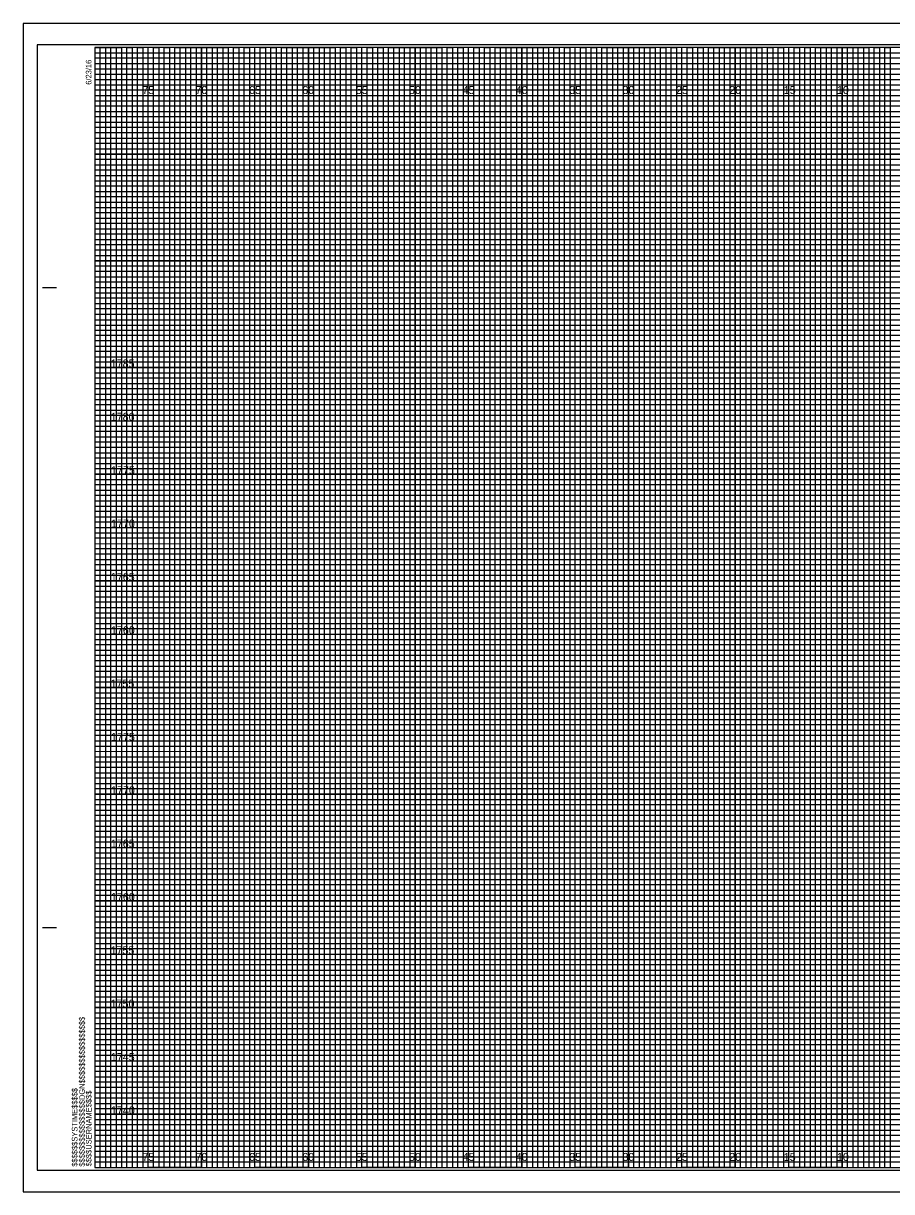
# Model space of a CAD drawing. Extents: x 224 to 392, y 1 to 440.
# Drawn here: x 223.6 to 304.9, y 221 to 330.5 of the extents above; entities that cross this region are included whole.
import ezdxf

# ---------------------------------------------------------------- set-up
doc = ezdxf.new("R2010")
doc.units = 0
for name, color, linetype in [('Prop Grid Mask', 7, 'Continuous'), ('Prop XS Elevation Labels', 7, 'Continuous'), ('Sheet Cross Section CELL', 7, 'Continuous'), ('Sheet Cross Section Grid Major CELL', 7, 'Continuous'), ('Sheet Cross Section Grid Middle CELL', 7, 'Continuous'), ('Sheet Cross Section Grid Minor 1 CELL', 7, 'Continuous'), ('Sheet Cross Section Grid Minor 2 CELL', 7, 'Continuous'), ('Sheet Cutting Line CELL', 7, 'Continuous'), ('Sheet DOT Grid CELL', 7, 'Continuous'), ('Sheet Plot Border Inside CELL', 7, 'Continuous'), ('Sheet Plot Border Outside CELL', 7, 'Continuous')]:
    doc.layers.add(name, color=color, linetype=linetype)

msp = doc.modelspace()

# ---------------------------------------------------------------- linework, layer by layer
at = {"layer": 'Sheet Cross Section CELL'}
for p, q in [((225.36, 305.71), (226.61, 305.71)), ((225.41, 305.71), (226.66, 305.71)), ((225.36, 245.71), (226.61, 245.71)), ((225.41, 245.71), (226.66, 245.71)), ((230.26, 223.21), (230.26, 223.21)), ((230.26, 223.21), (230.26, 223.21)), ((230.26, 223.21), (230.26, 223.21)), ((230.26, 223.21), (230.26, 223.21)), ((230.26, 223.21), (230.26, 223.21)), ((230.26, 223.21), (230.26, 223.21)), ((230.26, 223.21), (230.26, 223.21))]:
    msp.add_line(p, q, dxfattribs=at)
msp.add_lwpolyline([(390.26, 328.21), (230.26, 328.21), (230.26, 223.21), (390.26, 223.21)], close=True, dxfattribs=at)
at = {"layer": 'Sheet Cross Section Grid Major CELL'}
for p, q in [((235.26, 328.21), (230.26, 328.21)), ((235.26, 223.21), (235.26, 328.21)), ((245.26, 328.21), (240.26, 328.21)), ((240.26, 328.21), (240.26, 223.21)), ((245.26, 223.21), (245.26, 328.21)), ((255.26, 328.21), (250.26, 328.21)), ((250.26, 328.21), (250.26, 223.21)), ((255.26, 223.21), (255.26, 328.21)), ((265.26, 328.21), (260.26, 328.21)), ((260.26, 328.21), (260.26, 223.21)), ((265.26, 223.21), (265.26, 328.21)), ((275.26, 328.21), (270.26, 328.21)), ((270.26, 328.21), (270.26, 223.21)), ((275.26, 223.21), (275.26, 328.21)), ((285.26, 328.21), (280.26, 328.21)), ((280.26, 328.21), (280.26, 223.21)), ((285.26, 223.21), (285.26, 328.21)), ((295.26, 328.21), (290.26, 328.21)), ((290.26, 328.21), (290.26, 223.21)), ((295.26, 223.21), (295.26, 328.21)), ((305.26, 328.21), (300.26, 328.21)), ((300.26, 328.21), (300.26, 223.21)), ((240.26, 223.21), (235.26, 223.21)), ((250.26, 223.21), (245.26, 223.21)), ((260.26, 223.21), (255.26, 223.21)), ((270.26, 223.21), (265.26, 223.21)), ((280.26, 223.21), (275.26, 223.21)), ((290.26, 223.21), (285.26, 223.21)), ((300.26, 223.21), (295.26, 223.21))]:
    msp.add_line(p, q, dxfattribs=at)
for points in [[(230.26, 323.21), (390.26, 323.21), (390.26, 318.21), (230.26, 318.21)], [(230.26, 313.21), (390.26, 313.21), (390.26, 308.21), (230.26, 308.21)], [(230.26, 303.21), (390.26, 303.21), (390.26, 298.21), (230.26, 298.21)], [(230.26, 293.21), (390.26, 293.21), (390.26, 288.21), (230.26, 288.21)], [(230.26, 283.21), (390.26, 283.21), (390.26, 278.21), (230.26, 278.21)], [(230.26, 273.21), (390.26, 273.21), (390.26, 268.21), (230.26, 268.21)], [(230.26, 263.21), (390.26, 263.21), (390.26, 258.21), (230.26, 258.21)], [(230.26, 253.21), (390.26, 253.21), (390.26, 248.21), (230.26, 248.21)], [(230.26, 243.21), (390.26, 243.21), (390.26, 238.21), (230.26, 238.21)], [(230.26, 233.21), (390.26, 233.21), (390.26, 228.21), (230.26, 228.21)]]:
    msp.add_lwpolyline(points, dxfattribs=at)
at = {"layer": 'Sheet Cross Section Grid Middle CELL'}
for points in [[(230.26, 328.21), (232.76, 328.21), (232.76, 223.21), (237.76, 223.21), (237.76, 328.21), (242.76, 328.21), (242.76, 223.21), (247.76, 223.21), (247.76, 328.21), (252.76, 328.21), (252.76, 223.21), (257.76, 223.21), (257.76, 328.21), (262.76, 328.21), (262.76, 223.21), (267.76, 223.21), (267.76, 328.21), (272.76, 328.21), (272.76, 223.21), (277.76, 223.21), (277.76, 328.21), (282.76, 328.21), (282.76, 223.21), (287.76, 223.21), (287.76, 328.21), (292.76, 328.21), (292.76, 223.21), (297.76, 223.21), (297.76, 328.21), (302.76, 328.21), (302.76, 223.21), (307.76, 223.21)], [(230.26, 325.71), (367.76, 325.71)], [(230.26, 315.71), (390.26, 315.71), (390.26, 320.71), (230.26, 320.71)], [(230.26, 305.71), (390.26, 305.71), (390.26, 310.71), (230.26, 310.71)], [(230.26, 295.71), (390.26, 295.71), (390.26, 300.71), (230.26, 300.71)], [(230.26, 285.71), (390.26, 285.71), (390.26, 290.71), (230.26, 290.71)], [(230.26, 275.71), (390.26, 275.71), (390.26, 280.71), (230.26, 280.71)], [(230.26, 265.71), (390.26, 265.71), (390.26, 270.71), (230.26, 270.71)], [(230.26, 255.71), (390.26, 255.71), (390.26, 260.71), (230.26, 260.71)], [(230.26, 245.71), (390.26, 245.71), (390.26, 250.71), (230.26, 250.71)], [(230.26, 235.71), (390.26, 235.71), (390.26, 240.71), (230.26, 240.71)], [(230.26, 225.71), (390.26, 225.71), (390.26, 230.71), (230.26, 230.71)]]:
    msp.add_lwpolyline(points, dxfattribs=at)
at = {"layer": 'Sheet Cross Section Grid Minor 1 CELL'}
for p, q in [((230.26, 327.71), (360.26, 327.71)), ((360.26, 327.2), (230.26, 327.2)), ((230.26, 327.2), (230.26, 326.71)), ((230.26, 326.71), (360.26, 326.71)), ((360.26, 326.16), (230.26, 326.16)), ((230.26, 326.16), (230.26, 325.21)), ((230.26, 325.21), (390.26, 325.21))]:
    msp.add_line(p, q, dxfattribs=at)
for points in [[(230.26, 324.71), (365.26, 324.71), (390.26, 324.71), (390.26, 324.21), (230.26, 324.21)], [(230.26, 323.71), (390.26, 323.71), (390.26, 322.71), (230.26, 322.71)], [(230.26, 322.21), (390.26, 322.21), (390.26, 321.71), (230.26, 321.7)], [(230.26, 321.21), (390.26, 321.21), (390.26, 320.21), (230.26, 320.21)], [(230.26, 319.71), (390.26, 319.71), (390.26, 319.21), (230.26, 319.21)], [(230.26, 318.71), (390.26, 318.71), (390.26, 317.71), (230.26, 317.71)], [(230.26, 317.21), (390.26, 317.21), (390.26, 316.71), (230.26, 316.71)], [(230.26, 316.21), (390.26, 316.21), (390.26, 315.21), (230.26, 315.21)], [(230.26, 314.71), (390.26, 314.71), (390.26, 314.21), (230.26, 314.21)], [(230.26, 313.71), (390.26, 313.71), (390.26, 312.71), (230.26, 312.71)], [(230.26, 312.21), (390.26, 312.21), (390.26, 311.71), (230.26, 311.71)], [(230.26, 311.21), (390.26, 311.21), (390.26, 310.19), (390.26, 309.71), (390.26, 309.21), (230.26, 309.21)], [(230.26, 310.21), (390.26, 310.21), (390.26, 309.71), (230.26, 309.71)], [(230.26, 308.71), (390.26, 308.71), (390.26, 307.71), (230.26, 307.73)], [(230.26, 307.73), (390.26, 307.71), (390.26, 307.21), (230.26, 307.21)], [(230.26, 306.71), (390.26, 306.71), (390.26, 306.21), (230.26, 306.21)], [(230.26, 305.21), (390.26, 305.21), (390.26, 304.71), (230.26, 304.71)], [(230.26, 304.21), (390.26, 304.21), (390.26, 303.71), (230.26, 303.71)], [(230.23, 302.66), (390.26, 302.66), (390.26, 302.15), (230.23, 302.15)], [(230.26, 301.71), (390.26, 301.71), (390.26, 301.21), (230.26, 301.21)], [(230.26, 300.21), (390.26, 300.21), (390.26, 299.71), (230.26, 299.71)], [(230.26, 299.21), (390.26, 299.21), (390.26, 298.71), (230.26, 298.71)], [(230.26, 297.71), (390.26, 297.71), (390.26, 297.21), (230.26, 297.21)], [(230.26, 296.71), (390.26, 296.71), (390.26, 296.21), (230.26, 296.21)], [(230.26, 295.21), (390.26, 295.21), (390.26, 294.71), (230.26, 294.71)], [(230.26, 294.21), (390.26, 294.21), (390.26, 293.71), (230.26, 293.71)], [(230.26, 292.71), (390.26, 292.71), (390.26, 292.2), (230.26, 292.21)], [(230.26, 291.71), (390.26, 291.71), (390.26, 291.21), (230.26, 291.21)], [(230.26, 290.21), (390.26, 290.21), (390.26, 289.71), (230.26, 289.71)], [(230.26, 289.21), (390.26, 289.21), (390.26, 288.71), (230.26, 288.71)], [(230.26, 287.71), (390.26, 287.71), (390.26, 287.21), (230.26, 287.21)], [(230.26, 286.71), (390.26, 286.71), (390.26, 286.21), (230.26, 286.21)], [(230.26, 285.21), (390.26, 285.21), (390.26, 284.71), (230.26, 284.71)], [(230.26, 284.21), (390.26, 284.21), (390.26, 283.71), (230.26, 283.71)], [(230.26, 282.71), (390.26, 282.71), (390.26, 282.21), (230.26, 282.21)], [(230.26, 281.71), (390.3, 281.67), (390.26, 281.21), (230.26, 281.21)], [(230.26, 280.21), (390.26, 280.21), (390.26, 279.71), (230.26, 279.71)], [(230.26, 279.21), (390.26, 279.21), (390.26, 278.71), (230.26, 278.71)], [(230.26, 277.71), (390.26, 277.71), (390.26, 277.21), (230.26, 277.21)], [(230.26, 276.71), (390.26, 276.71), (390.26, 276.21), (230.26, 276.21)], [(230.26, 275.21), (390.26, 275.21), (390.26, 274.71), (230.26, 274.71)], [(230.26, 274.21), (390.26, 274.21), (390.26, 273.71), (230.26, 273.71)], [(230.26, 272.71), (390.26, 272.71), (390.26, 272.21), (230.26, 272.21)], [(230.26, 271.71), (390.26, 271.71), (390.26, 271.21), (230.26, 271.21)], [(230.26, 270.21), (390.26, 270.21), (390.26, 269.71), (230.26, 269.71)], [(230.26, 269.21), (390.26, 269.21), (390.26, 268.71), (230.26, 268.71)], [(230.26, 267.71), (390.26, 267.71), (390.26, 267.21), (230.26, 267.21)], [(230.26, 266.71), (390.26, 266.71), (390.26, 266.21), (230.26, 266.21)], [(230.26, 265.21), (390.26, 265.21), (390.26, 264.71), (230.26, 264.71)], [(230.26, 264.21), (390.26, 264.21), (390.26, 263.71), (230.26, 263.71)], [(230.26, 262.71), (390.26, 262.71), (390.26, 262.2), (230.26, 262.21)], [(230.26, 261.71), (390.26, 261.71), (390.26, 261.21), (230.26, 261.21)], [(230.26, 260.21), (390.26, 260.21), (390.26, 259.71), (230.26, 259.71)], [(230.26, 259.21), (390.26, 259.21), (390.26, 258.71), (230.26, 258.71)], [(230.26, 257.71), (390.26, 257.71), (390.26, 257.21), (230.26, 257.21)], [(230.26, 256.71), (390.26, 256.71), (390.26, 256.21), (230.26, 256.21)], [(230.26, 255.21), (390.26, 255.21), (390.26, 254.71), (230.26, 254.71)], [(230.26, 254.21), (390.26, 254.21), (390.26, 253.71), (230.26, 253.71)], [(230.26, 252.71), (390.26, 252.71), (390.26, 252.21), (230.26, 252.21)], [(230.26, 251.71), (390.3, 251.67), (390.26, 251.21), (230.26, 251.21)], [(230.26, 250.21), (390.26, 250.21), (390.26, 249.71), (230.26, 249.71)], [(230.26, 249.21), (390.26, 249.21), (390.26, 248.71), (230.26, 248.71)], [(230.26, 247.71), (390.26, 247.71), (390.26, 247.21), (230.26, 247.21)], [(230.26, 246.71), (390.26, 246.71), (390.26, 246.21), (230.26, 246.21)], [(230.26, 245.21), (390.26, 245.21), (390.26, 244.71), (230.26, 244.71)], [(230.26, 244.21), (390.26, 244.21), (390.26, 243.71), (230.26, 243.71)], [(230.26, 242.71), (390.26, 242.71), (390.26, 242.21), (230.26, 242.21)], [(230.26, 241.71), (390.26, 241.71), (390.26, 241.21), (230.26, 241.21)], [(230.26, 240.21), (390.26, 240.21), (390.26, 239.71), (230.26, 239.71)], [(230.26, 239.21), (390.26, 239.21), (390.26, 238.71), (230.26, 238.71)], [(230.26, 237.71), (390.26, 237.71), (390.26, 237.21), (230.26, 237.21)], [(230.26, 236.71), (390.26, 236.71), (390.26, 236.21), (230.26, 236.21)], [(230.26, 235.21), (390.26, 235.21), (390.26, 234.71), (230.26, 234.71)], [(230.26, 234.21), (390.26, 234.21), (390.26, 233.71), (230.26, 233.71)], [(230.26, 232.71), (390.26, 232.71), (390.26, 232.21), (230.26, 232.21)], [(230.26, 231.71), (390.26, 231.71), (390.26, 231.21), (230.26, 231.21)], [(230.26, 230.21), (390.26, 230.21), (390.26, 229.71), (230.26, 229.71)], [(230.26, 229.21), (390.26, 229.21), (390.26, 228.71), (230.26, 228.71)], [(230.26, 227.71), (390.26, 227.71), (390.26, 227.21), (230.26, 227.21)], [(230.26, 226.71), (390.26, 226.71), (390.26, 226.21), (230.26, 226.21)], [(230.26, 225.21), (390.26, 225.21), (390.26, 224.71), (230.26, 224.71)], [(230.26, 224.21), (390.26, 224.21), (390.26, 223.71), (230.26, 223.71)]]:
    msp.add_lwpolyline(points, dxfattribs=at)
at = {"layer": 'Sheet Cross Section Grid Minor 2 CELL'}
for points in [[(230.26, 223.21), (230.76, 223.21), (230.76, 328.21), (231.26, 328.21), (231.26, 223.21)], [(231.26, 223.21), (231.76, 223.21), (231.76, 328.21), (232.26, 328.21), (232.26, 223.21)], [(232.76, 223.21), (233.26, 223.21), (233.26, 328.21), (233.76, 328.21), (233.76, 223.21)], [(233.76, 223.21), (234.26, 223.21), (234.26, 328.21), (234.76, 328.21), (234.76, 223.21)], [(235.26, 223.21), (235.76, 223.21), (235.76, 328.21), (236.26, 328.21), (236.26, 223.21)], [(236.26, 223.21), (236.76, 223.21), (236.76, 328.21), (237.26, 328.21), (237.26, 223.21)], [(237.76, 223.21), (238.26, 223.21), (238.26, 328.21), (238.76, 328.21), (238.76, 223.21)], [(238.76, 223.21), (239.26, 223.21), (239.26, 328.21), (239.76, 328.21), (239.76, 223.21)], [(240.26, 223.21), (240.76, 223.21), (240.76, 328.21), (241.26, 328.21), (241.26, 223.21)], [(241.26, 223.21), (241.76, 223.21), (241.76, 328.21), (242.26, 328.21), (242.26, 223.21)], [(242.76, 223.21), (243.26, 223.21), (243.26, 328.21), (243.76, 328.21), (243.76, 223.21)], [(243.76, 223.21), (244.26, 223.21), (244.26, 328.21), (244.76, 328.21), (244.76, 223.21)], [(245.26, 223.21), (245.76, 223.21), (245.76, 328.21), (246.26, 328.21), (246.26, 223.21)], [(246.26, 223.21), (246.76, 223.21), (246.76, 328.21), (247.26, 328.21), (247.26, 223.21)], [(247.76, 223.21), (248.26, 223.21), (248.26, 328.21), (248.76, 328.21), (248.76, 223.21)], [(248.76, 223.21), (249.26, 223.21), (249.26, 328.21), (249.76, 328.21), (249.76, 223.21)], [(250.26, 223.21), (250.76, 223.21), (250.76, 328.21), (251.26, 328.21), (251.26, 223.21)], [(251.26, 223.21), (251.76, 223.21), (251.76, 328.21), (252.26, 328.21), (252.26, 223.21)], [(252.76, 223.21), (253.26, 223.21), (253.26, 328.21), (253.76, 328.21), (253.76, 223.21)], [(253.76, 223.21), (254.26, 223.21), (254.26, 328.21), (254.76, 328.21), (254.76, 223.21)], [(255.26, 223.21), (255.76, 223.21), (255.76, 328.21), (256.26, 328.21), (256.26, 223.21)], [(256.26, 223.21), (256.76, 223.21), (256.76, 328.21), (257.26, 328.21), (257.26, 223.21)], [(257.76, 223.21), (258.26, 223.21), (258.26, 328.21), (258.76, 328.21), (258.76, 223.21)], [(258.76, 223.21), (259.26, 223.21), (259.26, 328.21), (259.76, 328.21), (259.76, 223.21)], [(260.26, 223.21), (260.76, 223.21), (260.76, 328.21), (261.26, 328.21), (261.26, 223.21)], [(261.26, 223.21), (261.76, 223.21), (261.76, 328.21), (262.26, 328.21), (262.26, 223.21)], [(262.76, 223.21), (263.26, 223.21), (263.26, 328.21), (263.76, 328.21), (263.76, 223.21)], [(263.76, 223.21), (264.26, 223.21), (264.26, 328.21), (264.76, 328.21), (264.76, 223.21)], [(265.26, 223.21), (265.76, 223.21), (265.76, 328.21), (266.26, 328.21), (266.26, 223.21)], [(266.26, 223.21), (266.76, 223.21), (266.76, 328.21), (267.26, 328.21), (267.26, 223.21)], [(267.76, 223.21), (268.26, 223.21), (268.26, 328.21), (268.76, 328.21), (268.76, 223.21)], [(268.76, 223.21), (269.26, 223.21), (269.26, 328.21), (269.76, 328.21), (269.76, 223.21)], [(270.26, 223.21), (270.76, 223.21), (270.76, 328.21), (271.26, 328.21), (271.26, 223.21)], [(271.26, 223.21), (271.76, 223.21), (271.76, 328.21), (272.26, 328.21), (272.26, 223.21)], [(272.76, 223.21), (273.26, 223.21), (273.26, 328.21), (273.76, 328.21), (273.76, 223.21)], [(273.76, 223.21), (274.26, 223.21), (274.26, 328.21), (274.76, 328.21), (274.76, 223.21)], [(275.26, 223.21), (275.76, 223.21), (275.76, 328.21), (276.26, 328.21), (276.26, 223.21)], [(276.26, 223.21), (276.76, 223.21), (276.76, 328.21), (277.26, 328.21), (277.26, 223.21)], [(277.76, 223.21), (278.26, 223.21), (278.26, 328.21), (278.76, 328.21), (278.76, 223.21)], [(278.76, 223.21), (279.26, 223.21), (279.26, 328.21), (279.76, 328.21), (279.76, 223.21)], [(280.26, 223.21), (280.76, 223.21), (280.76, 328.21), (281.26, 328.21), (281.26, 223.21)], [(281.26, 223.21), (281.76, 223.21), (281.76, 328.21), (282.26, 328.21), (282.26, 223.21)], [(282.76, 223.21), (283.26, 223.21), (283.26, 328.21), (283.76, 328.21), (283.76, 223.21)], [(283.76, 223.21), (284.26, 223.21), (284.26, 328.21), (284.76, 328.21), (284.76, 223.21)], [(285.26, 223.21), (285.76, 223.21), (285.76, 328.21), (286.26, 328.21), (286.26, 223.21)], [(286.26, 223.21), (286.76, 223.21), (286.76, 328.21), (287.26, 328.21), (287.26, 223.21)], [(287.76, 223.21), (288.26, 223.21), (288.26, 328.21), (288.76, 328.21), (288.76, 223.21)], [(288.76, 223.21), (289.26, 223.21), (289.26, 328.21), (289.76, 328.21), (289.76, 223.21)], [(290.26, 223.21), (290.76, 223.21), (290.76, 328.21), (291.26, 328.21), (291.26, 223.21)], [(291.26, 223.21), (291.76, 223.21), (291.76, 328.21), (292.26, 328.21), (292.26, 223.21)], [(292.76, 223.21), (293.26, 223.21), (293.26, 328.21), (293.76, 328.21), (293.76, 223.21)], [(293.76, 223.21), (294.26, 223.21), (294.26, 328.21), (294.76, 328.21), (294.76, 223.21)], [(295.26, 223.21), (295.76, 223.21), (295.76, 328.21), (296.26, 328.21), (296.26, 223.21)], [(296.26, 223.21), (296.76, 223.21), (296.76, 328.21), (297.26, 328.21), (297.26, 223.21)], [(297.76, 223.21), (298.26, 223.21), (298.26, 328.21), (298.76, 328.21), (298.76, 223.21)], [(298.76, 223.21), (299.26, 223.21), (299.26, 328.21), (299.76, 328.21), (299.76, 223.21)], [(300.26, 223.21), (300.76, 223.21), (300.76, 328.21), (301.26, 328.21), (301.26, 223.21)], [(301.26, 223.21), (301.76, 223.21), (301.76, 328.21), (302.26, 328.21), (302.26, 223.21)], [(302.76, 223.21), (303.26, 223.21), (303.26, 328.21), (303.76, 328.21), (303.76, 223.21)], [(303.76, 223.21), (304.26, 223.21), (304.26, 328.21), (304.76, 328.21), (304.76, 223.21)]]:
    msp.add_lwpolyline(points, dxfattribs=at)
at = {"layer": 'Sheet Cutting Line CELL'}
for p, q in [((391.91, 330.46), (223.56, 330.46)), ((223.56, 330.46), (223.56, 220.96)), ((223.56, 220.96), (391.91, 220.96))]:
    msp.add_line(p, q, dxfattribs=at)
at = {"layer": 'Sheet DOT Grid CELL'}
for p, q in [((235.26, 223.21), (235.26, 328.21)), ((240.26, 223.21), (240.26, 328.21)), ((245.26, 223.21), (245.26, 328.21)), ((250.26, 223.21), (250.26, 328.21)), ((255.26, 223.21), (255.26, 328.21)), ((260.26, 223.21), (260.26, 328.21)), ((265.26, 223.21), (265.26, 328.21)), ((270.26, 223.21), (270.26, 328.21)), ((275.26, 223.21), (275.26, 328.21)), ((280.26, 223.21), (280.26, 328.21)), ((285.26, 223.21), (285.26, 328.21)), ((290.26, 223.21), (290.26, 328.21)), ((295.26, 223.21), (295.26, 328.21)), ((300.26, 223.21), (300.26, 328.21)), ((230.26, 323.21), (390.26, 323.21)), ((230.26, 318.21), (390.26, 318.21)), ((230.26, 313.21), (390.26, 313.21)), ((230.26, 308.21), (390.26, 308.21)), ((230.26, 303.21), (390.26, 303.21)), ((230.26, 298.21), (390.26, 298.21)), ((230.26, 293.21), (390.26, 293.21)), ((230.26, 288.21), (390.26, 288.21)), ((230.26, 283.21), (390.26, 283.21)), ((230.26, 278.21), (390.26, 278.21)), ((230.26, 273.21), (390.26, 273.21)), ((230.26, 268.21), (390.26, 268.21)), ((230.26, 263.21), (390.26, 263.21)), ((230.26, 258.21), (390.26, 258.21)), ((230.26, 253.21), (390.26, 253.21)), ((230.26, 248.21), (390.26, 248.21)), ((230.26, 243.21), (390.26, 243.21)), ((230.26, 238.21), (390.26, 238.21)), ((230.26, 233.21), (390.26, 233.21)), ((230.26, 228.21), (390.26, 228.21))]:
    msp.add_line(p, q, dxfattribs=at)
at = {"layer": 'Sheet Plot Border Inside CELL'}
msp.add_lwpolyline([(224.86, 222.96), (391.46, 222.96), (391.46, 328.46), (224.86, 328.46)], close=True, dxfattribs=at)
at = {"layer": 'Sheet Plot Border Outside CELL'}
msp.add_lwpolyline([(223.56, 220.96), (391.91, 220.96), (391.91, 330.46), (223.56, 330.46)], close=True, dxfattribs=at)

# ---------------------------------------------------------------- texts
at = {"layer": 'Prop Grid Mask'}
for s, p in [('75', (234.71, 323.84)), ('70', (239.69, 323.84)), ('65', (244.71, 323.84)), ('60', (249.69, 323.84)), ('55', (254.71, 323.84)), ('50', (259.69, 323.84)), ('45', (264.71, 323.84)), ('40', (269.69, 323.84)), ('35', (274.71, 323.84)), ('30', (279.69, 323.84)), ('25', (284.71, 323.84)), ('20', (289.69, 323.84)), ('15', (294.8, 323.84)), ('10', (299.78, 323.84)), ('75', (234.71, 223.84)), ('70', (239.69, 223.84)), ('65', (244.71, 223.84)), ('60', (249.69, 223.84)), ('55', (254.71, 223.84)), ('50', (259.69, 223.84)), ('45', (264.71, 223.84)), ('40', (269.69, 223.84)), ('35', (274.71, 223.84)), ('30', (279.69, 223.84)), ('25', (284.71, 223.84)), ('20', (289.69, 223.84)), ('15', (294.8, 223.84)), ('10', (299.78, 223.84))]:
    msp.add_text(s, height=0.75, dxfattribs=at).set_placement(p)
at = {"layer": 'Prop XS Elevation Labels'}
for s, p in [('1785', (231.75, 298.21)), ('1780', (231.75, 293.21)), ('1775', (231.78, 288.21)), ('1770', (231.78, 283.21)), ('1765', (231.76, 278.21)), ('1760', (231.77, 273.21)), ('1755', (231.73, 268.21)), ('1775', (231.78, 263.21)), ('1770', (231.78, 258.21)), ('1765', (231.76, 253.21)), ('1760', (231.77, 248.21)), ('1755', (231.73, 243.21)), ('1750', (231.74, 238.21)), ('1745', (231.76, 233.21)), ('1740', (231.77, 228.21))]:
    msp.add_text(s, height=0.75, dxfattribs=at).set_placement(p)
at = {"layer": 'Sheet Cross Section CELL'}
for s, p in [('6/23/16', (229.94, 324.71)), ('$$$$$$$$$$$$$$$$DGN$$$$$$$$$$$$$$$$', (229.32, 223.3)), ('$$$$$$SYSTIME$$$$$', (228.63, 223.3)), ('$$$$USERNAME$$$$', (229.95, 223.33))]:
    msp.add_text(s, height=0.525, rotation=90, dxfattribs=at).set_placement(p)

doc.saveas('drawing.dxf')
